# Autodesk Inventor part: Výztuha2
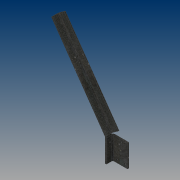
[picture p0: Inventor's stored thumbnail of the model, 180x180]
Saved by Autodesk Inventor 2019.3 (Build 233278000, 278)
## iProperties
Created: 2019-02
Part Number: Výztuha2
Material: Ocel, měkká, svařovaná
Document SubType Name: Plech
Designer: B-hon
Density: 7.85 g/cm^3
Sheet Metal Rule: Výchozí_mm
Appearance: Plech
Author: B-hon
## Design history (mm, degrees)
node "Plocha1"
  sketch "Náčrt1"
    geometry: L1 (-7, 0)-(-48, 0); L2 (-48, 0)-(-48, 310); L3 (-7, 310)-(-7, 0); L4 (-48, 310)-(-7, 310); 5 further points
    constraints: 8 end point, 2 horizontal alignment, 1 horizontal, 1 parallel, 1 perpendicular
    dimensions: "d5" = 7 vertical distance of point (0, 0) point (-17, 7); "d6" = 17 horizontal distance of point (0, 0) point (-17, 7); "d7" = 21 distance of point (-38, 7) point (-17, 7); "d8" = 45 vertical distance of point (-17, 7) point (-27.5, 52); "d9" = 10.5 horizontal distance of point (-17, 7) point (-27.5, 52) (= 0.5 x d7); "d10" = 10 distance from line of point (-17, 7) L3; "d11" = 10 distance from line of point (-38, 7) L2 (= d10); "d12" = 250 distance from line of L3 point (243, 370); "d13" = 370 distance from line of L1 point (243, 370); "d15" = 310 distance of L1.end L2.end
node "Obruba4"
sketch "Náčrt9"
  geometry: L1 (14, 0)-(14, 310) reference; L2 (29.659, 62)-(14, 62); L3 (14, 62)-(14, 60); L4 (14, 60)-(29.659, 60); L5 (29.659, 60)-(29.659, 62); L6 (17, 0)-(14, 0) reference; 1 further point
  constraints: 8 end point, 2 parallel, 1 horizontal, 1 perpendicular, 1 point on line
  dimensions: "d83" = 2 distance of L4.end L2.start; "d84" = 60 distance between parallel lines of L6 L4
extrude "Vysunutí2" cut sketch "Náčrt9" stored distance "d85" = 200; taper "d86" = 0 deg
sketch "Náčrt10"
  geometry: L1 (-67.25, 60)-(25.208, 60); L2 (-20, 60)-(-14, 60) reference; 1 further point
  constraints: 2 end point, 1 collinear
  dimensions: "d87" = 0 distance between parallel lines of L1 L2
feature "Ohyb součásti2" sketch "Náčrt10" dims "d88" = 3, "d89" = 35 deg
node "Upravit přímo2"
sketch "Náčrt11"
  geometry: L1 (48, 60)-(48, 0) reference; L2 (7, 0)-(42, 0) reference; 4 further points
  constraints: 1 horizontal alignment
  dimensions: "d93" = 14 distance from line of point (34, 7) L1; "d94" = 7 distance from line of L2 point (34, 7); "d95" = 21 distance of point (34, 7) point (13, 7); "d96" = 45 vertical distance of point (34, 7) point (23.5, 52); "d97" = 10.5 horizontal distance of point (34, 7) point (23.5, 52) (= 0.5 x d95)
hole "Díra2" sketch "Náčrt11" at (34, 7), (13, 7), (23.5, 52) diameter "d98" = 5.5; stored, may be unused: countersink angle "d102" = 90 deg, drill point angle "d104" = 0 deg; dims "d99" = 6, "d100" = 4, "d101" = 2, "d103" = 3 (= Tloušťka)
node "Upravit přímo3"
node "Těleso1"
feature "Deska1" dims "d14" = 3 (= Tloušťka)
sketch "Náčrt8"
  geometry: L1 through (-155, 0) direction (1, 1.41e-48); L2 through (0, 10) direction (1.23e-32, 1); L3 (0, 20)-(-310, 20); L4 (-310, 20)-(-310, 0)
  constraints: 6 end point, 1 horizontal, 1 perpendicular, 1 vertical
feature "Deska5" dims "d14" = 3 (= Tloušťka), "d73" = 3 (= ŠířkaVýštipu), "d74" = 1.5 (= HloubkaVýštipu), "d75" = 6 (= MinimálníZbytek), "d76" = 3 (= PřechodovýPoloměr), "d77" = 20, "d78" = 90 deg, "d79" = 3 (= PoloměrOhybu), "d80" = 12 (= VelikostRohovéhoVýštipu), "d81" = 3 (= VelikostMezery), "d82" = 3 (= VelikostJacobihoPoloměru), "MezeraVystřižení" = 0.01
feature "Ohyb4" dims "d14" = 3 (= Tloušťka), "d73" = 3 (= ŠířkaVýštipu), "d74" = 1.5 (= HloubkaVýštipu), "d75" = 6 (= MinimálníZbytek), "d76" = 3 (= PřechodovýPoloměr), "d77" = 20, "d78" = 90 deg, "d79" = 3 (= PoloměrOhybu), "MezeraVystřižení" = 0.01
feature "Roh4" dims "d77" = 20, "d78" = 90 deg, "d80" = 12 (= VelikostRohovéhoVýštipu), "d81" = 3 (= VelikostMezery), "d82" = 3 (= VelikostJacobihoPoloměru)
feature "Posunout2" dims "d92" = -20
feature "Posunout3" dims "d107" = 1
other parameters: "Tloušťka" = 3 (derived), "KSoučinitel" = 4.4, "PoloměrOhybu" = 3 (= Tloušťka), "ŠířkaVýštipu" = 3 (= Tloušťka), "HloubkaVýštipu" = 1.5 (= 0.5 x Tloušťka), "VelikostRohovéhoVýštipu" = 12 (= 4 x Tloušťka), "MinimálníZbytek" = 6 (= 2 x Tloušťka), "PřechodovýPoloměr" = 3 (= PoloměrOhybu), "VelikostJacobihoPoloměru" = 3 (= PoloměrOhybu), "VelikostMezery" = 3 (= Tloušťka), "d90" = 0, "d91" = 0, "d105" = 0, "d106" = 0
